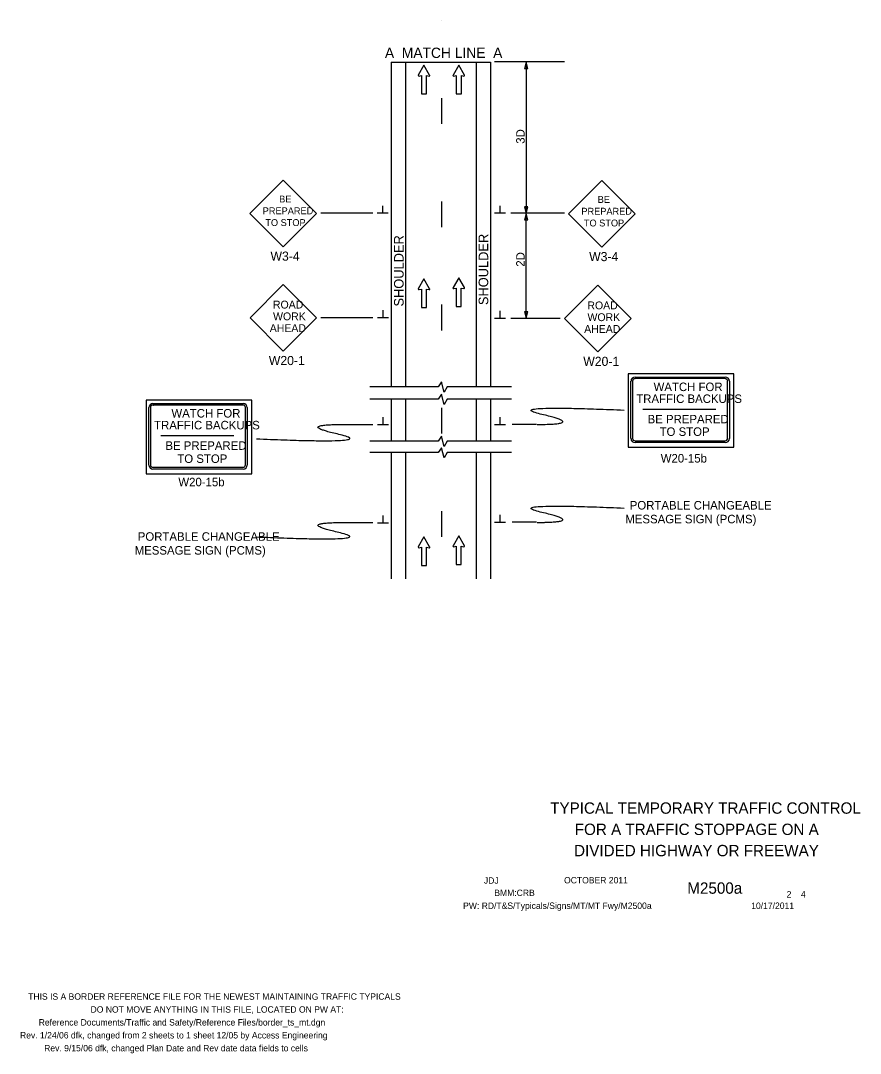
# Model space of a CAD drawing. Extents: x -1809 to 1554, y -1087 to 323.
# Drawn here: x -959 to -146, y -1087 to -86 of the extents above; entities that cross this region are included whole.
import ezdxf

# ---------------------------------------------------------------- set-up
doc = ezdxf.new("R2010")
doc.units = 0
for name, color, linetype in [('BORDER', 7, 'Continuous'), ('BORDER_SIGNAL_WO', 7, 'Continuous'), ('MT_SCRATCH_LEVEL_A', 7, 'Continuous'), ('MT_SCRATCH_LEVEL_E', 7, 'Continuous'), ('PAVT_EDGE_EX', 7, 'Continuous'), ('PAVT_EDGE_PR', 7, 'Continuous'), ('SCRATCH_LEVEL_A', 7, 'Continuous'), ('TRAFFIC_SIGNS_PR', 7, 'Continuous'), ('TYPICAL_EX', 7, 'Continuous'), ('TYPICAL_TEXT_DIMEN_EX', 7, 'Continuous'), ('TYPICAL_TEXT_DIMEN_PR', 7, 'Continuous')]:
    doc.layers.add(name, color=color, linetype=linetype)

msp = doc.modelspace()

# ---------------------------------------------------------------- linework, layer by layer
at = {"layer": 'BORDER'}
for p, q in [((-517.7, -126.4), (-517.7, -440.6)), ((-517.7, -453), (-517.7, -493.7)), ((-517.7, -505.1), (-517.7, -627))]:
    msp.add_line(p, q, dxfattribs=at)
at = {"layer": 'BORDER_SIGNAL_WO'}
for p, q in [((-551.2, -86.3), (-551.2, -86.3)), ((-551.2, -161.3), (-551.2, -186.3)), ((-551.2, -261.3), (-551.2, -286.3)), ((-551.2, -361.3), (-551.2, -386.3)), ((-551.2, -461.3), (-551.2, -486.3)), ((-551.2, -561.3), (-551.2, -586.3))]:
    msp.add_line(p, q, dxfattribs=at)
at = {"layer": 'MT_SCRATCH_LEVEL_A'}
for p, q in [((-586.1, -126.4), (-586.1, -440.6)), ((-586.1, -453.6), (-586.1, -493.7)), ((-586.1, -505.1), (-586.1, -627))]:
    msp.add_line(p, q, dxfattribs=at)
at = {"layer": 'MT_SCRATCH_LEVEL_E'}
for p, q in [((-568.3, -129.3), (-573.8, -139)), ((-562.8, -139), (-568.3, -129.3)), ((-534.6, -129.3), (-540.1, -139)), ((-529.1, -139), (-534.6, -129.3)), ((-573.1, -139.9), (-570.8, -139.5)), ((-570.8, -139.5), (-570.8, -157.1)), ((-565.8, -157.1), (-565.8, -139.5)), ((-565.8, -139.5), (-563.4, -139.9)), ((-539.5, -139.9), (-537.1, -139.5)), ((-537.1, -139.5), (-537.1, -157.1)), ((-532.1, -157.1), (-532.1, -139.5)), ((-532.1, -139.5), (-529.7, -139.9)), ((-570.8, -157.1), (-565.8, -157.1)), ((-537.1, -157.1), (-532.1, -157.1)), ((-568.3, -336.3), (-573.8, -345.9)), ((-562.8, -345.9), (-568.3, -336.3)), ((-534.7, -335.3), (-540.2, -344.9)), ((-529.1, -344.9), (-534.7, -335.3)), ((-573.1, -346.8), (-570.8, -346.4)), ((-570.8, -346.4), (-570.8, -364.1)), ((-565.8, -364.1), (-565.8, -346.4)), ((-565.8, -346.4), (-563.4, -346.8)), ((-539.5, -345.8), (-537.1, -345.4)), ((-537.1, -345.4), (-537.1, -363.1)), ((-532.2, -363.1), (-532.2, -345.4)), ((-532.2, -345.4), (-529.8, -345.8)), ((-570.8, -364.1), (-565.8, -364.1)), ((-537.1, -363.1), (-532.2, -363.1)), ((-568.3, -586.3), (-573.8, -595.9)), ((-562.8, -595.9), (-568.3, -586.3)), ((-534.7, -585.3), (-540.2, -594.9)), ((-529.1, -594.9), (-534.7, -585.3)), ((-573.1, -596.8), (-570.8, -596.4)), ((-570.8, -596.4), (-570.8, -614.1)), ((-565.8, -614.1), (-565.8, -596.4)), ((-565.8, -596.4), (-563.4, -596.8)), ((-539.5, -595.8), (-537.1, -595.4)), ((-537.1, -595.4), (-537.1, -613.1)), ((-532.2, -613.1), (-532.2, -595.4)), ((-532.2, -595.4), (-529.8, -595.8)), ((-570.8, -614.1), (-565.8, -614.1)), ((-537.1, -613.1), (-532.2, -613.1))]:
    msp.add_line(p, q, dxfattribs=at)
for centre, start, end in [((-573.2, -139.3), 150.4248, 279.9638), ((-563.3, -139.3), 260.0362, 29.7731), ((-539.6, -139.3), 150.4248, 279.9638), ((-529.6, -139.3), 260.0362, 29.7731), ((-573.2, -346.2), 150.4248, 279.9638), ((-563.3, -346.2), 260.0362, 29.7731), ((-539.6, -345.2), 150.4248, 279.9638), ((-529.7, -345.2), 260.0362, 29.7731), ((-573.2, -596.2), 150.4248, 279.9638), ((-563.3, -596.2), 260.0362, 29.7731), ((-539.6, -595.2), 150.4248, 279.9638), ((-529.7, -595.2), 260.0362, 29.7731)]:
    msp.add_arc(centre, 0.617, start, end, dxfattribs=at)
at = {"layer": 'PAVT_EDGE_EX'}
for p, q in [((-600, -126.4), (-600, -440.6)), ((-600, -126.4), (-540.2, -126.4)), ((-540.2, -126.4), (-503.8, -126.4)), ((-503.8, -126.4), (-503.8, -440.6)), ((-600, -453.3), (-600, -493.7)), ((-503.8, -453), (-503.8, -493.7)), ((-600, -505.1), (-600, -627)), ((-503.8, -505.2), (-503.8, -627))]:
    msp.add_line(p, q, dxfattribs=at)
at = {"layer": 'PAVT_EDGE_PR'}
msp.add_line((-534.7, -335.3), (-534.7, -335.3), dxfattribs=at)
at = {"layer": 'TRAFFIC_SIGNS_PR'}
for p, q in [((-704.7, -240.8), (-736.9, -273)), ((-672.4, -273), (-704.7, -240.8)), ((-396.2, -241.1), (-428.5, -273.4)), ((-364, -273.4), (-396.2, -241.1)), ((-736.9, -273), (-704.7, -305.3)), ((-704.7, -305.3), (-672.4, -273)), ((-428.5, -273.4), (-396.2, -305.6)), ((-396.2, -305.6), (-364, -273.4)), ((-704.5, -341.8), (-736.7, -374.1)), ((-672.2, -374.1), (-704.5, -341.8)), ((-400.1, -342.6), (-432.3, -374.8)), ((-367.8, -374.8), (-400.1, -342.6)), ((-736.7, -374.1), (-704.5, -406.3)), ((-704.5, -406.3), (-672.2, -374.1)), ((-432.3, -374.8), (-400.1, -407.1)), ((-400.1, -407.1), (-367.8, -374.8)), ((-356.3, -462.6), (-285.6, -462.6)), ((-345.6, -463), (-345.6, -463)), ((-823.1, -488.2), (-752.4, -488.2)), ((-812.4, -488.7), (-812.4, -488.7))]:
    msp.add_line(p, q, dxfattribs=at)
for points in [[(-370.6, -499.4), (-268.2, -499.4), (-268.2, -428.4), (-370.6, -428.4)], [(-837.4, -525.1), (-735, -525.1), (-735, -454), (-837.4, -454)]]:
    msp.add_lwpolyline(points, close=True, dxfattribs=at)
for points in [[(-367.9, -491), (-367.9, -435.5), (-367.9, -435.5)], [(-366.3, -435.4), (-366.3, -435.8), (-366.3, -436), (-366.3, -436.1), (-366.3, -436.2), (-366.3, -490.9)], [(-366.3, -435.8), (-366.3, -435.8)], [(-363.2, -433), (-364, -433)], [(-363.9, -431.5), (-363.9, -431.5), (-363.8, -431.5), (-363.7, -431.5), (-276.6, -431.5)], [(-363.2, -433), (-363.2, -433)], [(-363.2, -433), (-363.2, -433)], [(-276.6, -433), (-363.2, -433)], [(-274.3, -490.9), (-274.3, -435.4)], [(-272.6, -435.5), (-272.6, -491)], [(-830, -458.7), (-830.8, -458.7)], [(-830.7, -457.1), (-830.7, -457.1), (-830.6, -457.1), (-830.5, -457.1), (-743.4, -457.1)], [(-830, -458.7), (-830, -458.7)], [(-830, -458.7), (-830, -458.7)], [(-743.4, -458.7), (-830, -458.7)], [(-834.7, -516.7), (-834.7, -461.1), (-834.7, -461.1)], [(-833.1, -461), (-833.1, -461.4), (-833.1, -461.6), (-833.1, -461.7), (-833.1, -461.8), (-833.1, -516.6)], [(-833.1, -461.4), (-833.1, -461.4)], [(-741.1, -516.6), (-741.1, -461)], [(-739.4, -461.1), (-739.4, -516.7)], [(-364, -493.3), (-276.6, -493.3)], [(-276.6, -495), (-363.9, -495)], [(-830.8, -518.9), (-743.4, -518.9)], [(-743.4, -520.6), (-830.7, -520.6)]]:
    msp.add_lwpolyline(points, dxfattribs=at)
for centre, radius, start, end in [((-363.9, -435.5), 3.97, 90.2048, 180), ((-364, -435.4), 2.32, 90, 180), ((-363.6, -430.1), 2.95, 277.8103, 278.054), ((-276.6, -435.5), 3.97, 360, 90), ((-276.6, -435.4), 2.32, 0, 90), ((-830.7, -461.1), 3.97, 90.2048, 180), ((-830.8, -461), 2.32, 90, 180), ((-830.4, -455.7), 2.95, 277.8103, 278.054), ((-743.4, -461.1), 3.97, 360, 90), ((-743.4, -461), 2.32, 0, 90), ((-363.9, -491), 3.97, 180, 270), ((-364, -490.9), 2.32, 180, 270), ((-276.6, -490.9), 2.32, 270, 360), ((-276.6, -491), 3.97, 270, 0), ((-830.7, -516.7), 3.97, 180, 270), ((-830.8, -516.6), 2.32, 180, 270), ((-743.4, -516.6), 2.32, 270, 360), ((-743.4, -516.7), 3.97, 270, 0)]:
    msp.add_arc(centre, radius, start, end, dxfattribs=at)
for points in [[(-370.6, -454.7), (-370.5, -454.7), (-370.4, -454.7), (-370.3, -454.7)], [(-837.4, -480.3), (-837.3, -480.3), (-837.2, -480.3), (-837.1, -480.3)]]:
    msp.add_open_spline(points, degree=2, dxfattribs=at)
at = {"layer": 'TYPICAL_EX'}
for p, q in [((-608.2, -272.9), (-608.2, -265.5)), ((-494.7, -272.9), (-494.7, -265.5)), ((-608.2, -272.9), (-613.6, -272.9)), ((-602.9, -272.9), (-608.2, -272.9)), ((-494.7, -272.9), (-500, -272.9)), ((-489.3, -272.9), (-494.7, -272.9)), ((-607.9, -374.2), (-607.9, -366.8)), ((-494.7, -374.9), (-494.7, -367.5)), ((-607.9, -374.2), (-613.2, -374.2)), ((-602.5, -374.2), (-607.9, -374.2)), ((-494.7, -374.9), (-500, -374.9)), ((-489.3, -374.9), (-494.7, -374.9)), ((-607.9, -477.8), (-613.2, -477.8)), ((-607.9, -477.8), (-607.9, -470.4)), ((-602.5, -477.8), (-607.9, -477.8)), ((-494.7, -477.8), (-500, -477.8)), ((-494.7, -477.8), (-494.7, -470.4)), ((-489.3, -477.8), (-494.7, -477.8)), ((-607.9, -573), (-607.9, -565.6)), ((-494.7, -572.4), (-494.7, -565)), ((-607.9, -573), (-613.2, -573)), ((-602.5, -573), (-607.9, -573)), ((-494.7, -572.4), (-500, -572.4)), ((-489.3, -572.4), (-494.7, -572.4))]:
    msp.add_line(p, q, dxfattribs=at)
at = {"layer": 'TYPICAL_TEXT_DIMEN_PR'}
for p, q in [((-432.4, -126.2), (-500, -126.2)), ((-469.4, -126.3), (-471.1, -132.7)), ((-469.4, -126.3), (-469.4, -272.9)), ((-467.7, -132.7), (-469.4, -126.3)), ((-471.1, -132.7), (-469.4, -132.7)), ((-469.4, -132.7), (-467.7, -132.7)), ((-469.4, -266.5), (-471.1, -266.5)), ((-471.1, -266.5), (-469.4, -272.9)), ((-469.4, -272.9), (-467.7, -266.5)), ((-467.7, -266.5), (-469.4, -266.5)), ((-617.7, -272.9), (-668.1, -272.9)), ((-432.4, -272.9), (-484.1, -272.9)), ((-469.4, -272.9), (-471.1, -279.3)), ((-471.1, -279.3), (-469.4, -279.3)), ((-467.7, -279.3), (-469.4, -272.9)), ((-469.4, -374.8), (-469.4, -272.9)), ((-469.4, -279.3), (-467.7, -279.3)), ((-469.4, -368.4), (-471.1, -368.4)), ((-471.1, -368.4), (-469.4, -374.8)), ((-469.4, -374.8), (-467.7, -368.4)), ((-467.7, -368.4), (-469.4, -368.4)), ((-617.7, -374.2), (-668.1, -374.2)), ((-436.4, -374.8), (-484.1, -374.8)), ((-551.5, -436.2), (-554.7, -441)), ((-548.7, -446.2), (-551.5, -436.2)), ((-554.7, -441), (-620.7, -441)), ((-551.5, -448.2), (-554.7, -453)), ((-548.7, -458.1), (-551.5, -448.2)), ((-546, -441), (-548.7, -446.2)), ((-483.6, -441), (-546, -441)), ((-554.7, -453), (-620.7, -453)), ((-546, -453), (-548.7, -458.1)), ((-483.6, -453), (-546, -453)), ((-646.3, -477.4), (-617.7, -477.4)), ((-459.3, -477.6), (-483, -477.6)), ((-551.5, -488.9), (-554.7, -493.7)), ((-548.7, -498.8), (-551.5, -488.9)), ((-554.7, -493.7), (-620.7, -493.7)), ((-551.5, -499.9), (-554.7, -504.7)), ((-548.7, -509.9), (-551.5, -499.9)), ((-546, -493.7), (-548.7, -498.8)), ((-483.6, -493.7), (-546, -493.7)), ((-554.7, -504.7), (-620.7, -504.7)), ((-546, -504.7), (-548.7, -509.9)), ((-483.6, -504.7), (-546, -504.7)), ((-646.3, -572.4), (-617.7, -572.4)), ((-459.3, -572.2), (-483, -572.2))]:
    msp.add_line(p, q, dxfattribs=at)
for points in [[(-458.8, -477.4), (-411.7, -477.4), (-496, -458.2), (-374.6, -463.5)], [(-730.6, -491.3), (-608.7, -496.6), (-693.2, -477.4), (-646.1, -477.4)], [(-458.8, -572.3), (-411.7, -572.3), (-496, -553.1), (-374.6, -558.4)], [(-730.6, -586.3), (-608.7, -591.7), (-693.2, -572.4), (-646.1, -572.4)]]:
    msp.add_open_spline(points, degree=2, dxfattribs=at)

# ---------------------------------------------------------------- texts
at = {"layer": 'BORDER_SIGNAL_WO'}
for s, height, p in [(' TYPICAL TEMPORARY TRAFFIC CONTROL', 11, (-450.2, -854.5)), ('FOR A TRAFFIC STOPPAGE ON A', 11, (-422.3, -875.1)), ('DIVIDED HIGHWAY OR FREEWAY ', 11, (-423, -895.7)), ('JDJ         ', 6.2, (-510.3, -922.3)), ('    OCTOBER 2011', 6.2, (-441.9, -922)), ('BMM:CRB', 6.2, (-500.2, -934.2)), (' 2    4 ', 6.2, (-219.5, -935.7)), ('PW: RD/T&S/Typicals/Signs/MT/MT Fwy/M2500a        ', 6.2, (-530.4, -946.7)), ('10/17/2011', 6.2, (-251.5, -946.7))]:
    msp.add_text(s, height=height, dxfattribs=at).set_placement(p)
at = {"layer": 'SCRATCH_LEVEL_A'}
for s, p in [('THIS IS A BORDER REFERENCE FILE FOR THE NEWEST MAINTAINING TRAFFIC TYPICALS', (-951.5, -1034.7)), ('DO NOT MOVE ANYTHING IN THIS FILE, LOCATED ON PW AT:', (-891.1, -1047.2)), ('Reference Documents/Traffic and Safety/Reference Files/border_ts_mt.dgn', (-941.3, -1059.7)), ('Rev. 1/24/06 dfk, changed from 2 sheets to 1 sheet 12/05 by Access Engineering', (-959.4, -1072.2)), ('Rev. 9/15/06 dfk, changed Plan Date and Rev date data fields to cells', (-936, -1084.7))]:
    msp.add_text(s, height=6.2, dxfattribs=at).set_placement(p)
at = {"layer": 'TRAFFIC_SIGNS_PR'}
for s, height, p in [('BE', 6.65, (-708.5, -262.4)), ('BE', 6.65, (-400.1, -262.8)), ('PREPARED', 6.65, (-724.4, -273.8)), ('PREPARED', 6.65, (-415.9, -274.2)), ('TO STOP', 6.65, (-721.9, -285.2)), ('TO STOP', 6.65, (-413.5, -285.6)), ('W3-4', 8.84, (-716.9, -318.8)), ('W3-4', 8.84, (-408.4, -319.2)), ('ROAD', 7.6, (-714.5, -365.1)), ('ROAD', 7.6, (-410.1, -365.9)), ('WORK', 7.6, (-714.4, -376.5)), ('WORK', 7.6, (-410, -377.3)), ('AHEAD', 7.6, (-717.6, -387.9)), ('AHEAD', 7.6, (-413.2, -388.7)), ('W20-1', 8.84, (-718.5, -419.9)), ('W20-1', 8.84, (-414.1, -420.7)), ('WATCH FOR', 8.25, (-346, -445.1)), ('TRAFFIC BACKUPS', 8.25, (-362.8, -456.6)), ('WATCH FOR', 8.25, (-812.8, -470.7)), ('BE PREPARED', 8.25, (-351.8, -476.4)), ('TRAFFIC BACKUPS', 8.25, (-829.6, -482.2)), ('TO STOP', 8.25, (-340.2, -488.5)), ('BE PREPARED', 8.25, (-818.6, -502)), ('TO STOP', 8.25, (-807.1, -514.7)), ('W20-15b', 8.25, (-339.1, -514.3)), ('W20-15b', 8.25, (-806.1, -537.3)), ('PORTABLE CHANGEABLE', 8.25, (-369.1, -559.8)), ('  MESSAGE SIGN (PCMS)', 8.25, (-379.5, -573.2)), ('PORTABLE CHANGEABLE', 8.25, (-845.4, -590.1)), ('  MESSAGE SIGN (PCMS)', 8.25, (-854.5, -603.5))]:
    msp.add_text(s, height=height, dxfattribs=at).set_placement(p)
at = {"layer": 'TYPICAL_TEXT_DIMEN_EX'}
msp.add_text('A  MATCH LINE  A', height=10, dxfattribs=at).set_placement((-606.1, -122.4))
for p in [(-588, -363.2), (-506.1, -361.8)]:
    msp.add_text('SHOULDER', height=9.3, rotation=90, dxfattribs=at).set_placement(p)
at = {"layer": 'TYPICAL_TEXT_DIMEN_PR'}
for s, p in [('3D', (-470.8, -205.5)), ('2D', (-470.8, -324.6))]:
    msp.add_text(s, height=8.25, rotation=90, dxfattribs=at).set_placement(p)
msp.add_text('    M2500a   ', height=11, dxfattribs=at).set_placement((-329.7, -932))

doc.saveas('drawing.dxf')
